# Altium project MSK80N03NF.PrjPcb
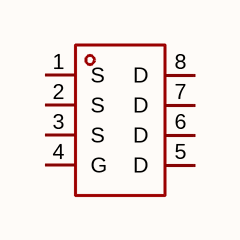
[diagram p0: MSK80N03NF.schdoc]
1 sheet, 1 parts. Net scope: global (net labels, ports and power ports of the same name join across sheets).

## Sheet MSK80N03NF.schdoc
size 127 x 101 mm

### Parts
Q?  msk80n03nf  [PDFN-8_L5.8-W5.0-P1.27-LS6.0-BL]  (value not drawn)

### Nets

Not connected (* = marked no-connect by the designer): Q? 1(S) 2(S) 3(S) 4(G) 5(D) 6(D) 7(D) 8(D)

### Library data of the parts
Q? = msk80n03nf: 数量:1个N沟道;漏源电压(Vdss):30V;连续漏极电流(Id):80A;导通电阻(RDS(on)):3.6mΩ@10V；4.5mΩ@4.5V;耗散功率(Pd):45W;阈值电压(Vgs(th)):1.6V;; Manufacturer: MSKSEMI(美森科); AddInBom: yes; ModelId: 64dd0a0ad16f4146a485008a6fd3b168; ModelTransform: 193.7004,238.189,0,0,0,0,0,0,0; Number: 1个N沟道; Drain to Source Voltage: 30V; Current - Continuous Drain(Id): 80A; Pd - Power Dissipation: 45W; Gate Threshold Voltage (Vgs(th)): 1.6V; Gate Charge(Qg): 11.1nC@4.5V; Input Capacitance(Ciss): 1.21nF; Reverse Transfer Capacitance (Crss@Vds): 100pF; Type: N沟道; Output Capacitance(Coss): 190pF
